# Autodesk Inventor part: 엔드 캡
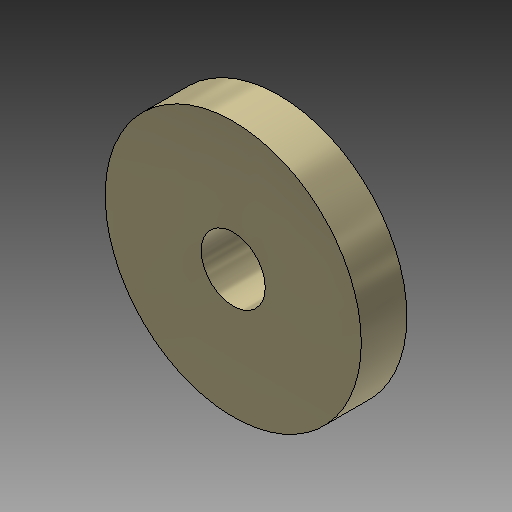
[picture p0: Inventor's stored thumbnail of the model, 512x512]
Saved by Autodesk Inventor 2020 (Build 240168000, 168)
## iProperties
Created: 2024-01
Part Number: 엔드 캡
Material: 강철, 연강
Document SubType Name: Modeling
Designer: mdu-01
Density: 1 g/cm^3
Appearance: 강철(1)
Author: mdu-01
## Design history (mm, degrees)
sketch "스케치1"
  geometry: C1 r 9 at (0, 0); 1 further point
  constraints: 1 centre point, 1 coincident
  dimensions: "d0" = 18 diameter of C1
extrude "돌출1" new body sketch "스케치1" distance "d1" = 3.2; taper "d2" = 0 deg
hole "구멍1" diameter "d5" = 4.5; stored, may be unused: countersink angle "d9" = 90 deg, drill point angle "d11" = 118 deg; dims "d3" = 10, "d4" = 10, "d6" = 6, "d7" = 9.4, "d8" = 2, "d10" = 8
node "솔리드1"
